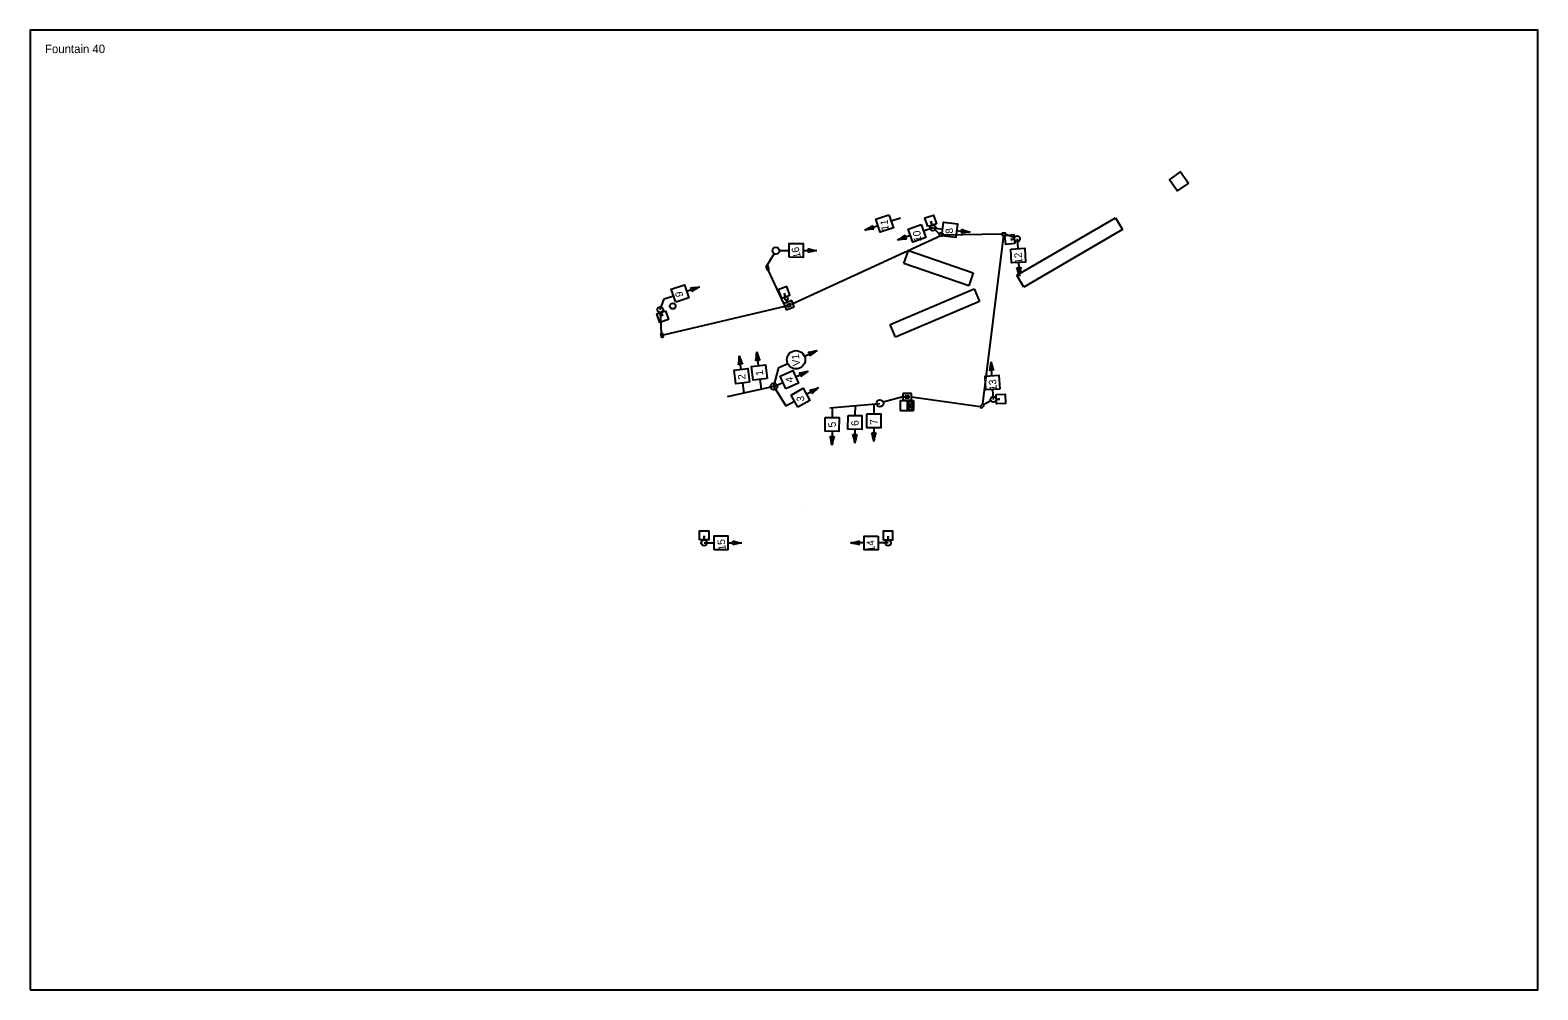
# Model space of a CAD drawing. Extents: x 994065 to 999017, y 1985203 to 1987174.
# Drawn here: x 994673 to 995333, y 1986754 to 1987174 of the extents above; entities that cross this region are included whole.
import ezdxf

# ---------------------------------------------------------------- set-up
doc = ezdxf.new("R2010")
doc.units = 0
for name, color, linetype in [('DSN_DRAIN_Analytics', 7, 'Continuous'), ('DSN_DRAIN_Analytics_ArDOT_BMCD_Rt', 7, 'Continuous'), ('DSN_DRAIN_Storm-Sewer', 7, 'Continuous'), ('EX_CONTOUR_ANNOT_MAJOR', 7, 'Continuous'), ('EX_CONTOUR_ANNOT_MINOR', 7, 'Continuous'), ('EX_TERRAIN', 7, 'Continuous'), ('EX_TERRAIN_BOUNDARY', 7, 'Continuous'), ('Level 23', 7, 'Continuous')]:
    doc.layers.add(name, color=color, linetype=linetype)

msp = doc.modelspace()

# ---------------------------------------------------------------- linework, layer by layer
at = {"layer": 'DSN_DRAIN_Analytics'}
for p, q in [((995105.13, 1987066.54), (995148.32, 1987091.73)), ((995148.32, 1987091.73), (995151.35, 1987086.55)), ((995151.35, 1987086.55), (995108.16, 1987061.35)), ((995055.7, 1987071.69), (995057.65, 1987077.37)), ((995057.65, 1987077.37), (995086.02, 1987067.63)), ((995084.07, 1987061.95), (995055.7, 1987071.69)), ((995086.02, 1987067.63), (995084.07, 1987061.95)), ((995108.16, 1987061.35), (995105.13, 1987066.54)), ((995049.65, 1987044.93), (995086.46, 1987060.61)), ((995086.46, 1987060.61), (995088.81, 1987055.09)), ((995088.81, 1987055.09), (995052.01, 1987039.41)), ((995052.01, 1987039.41), (995049.65, 1987044.93))]:
    msp.add_line(p, q, dxfattribs=at)
msp.add_lwpolyline([(995180.24, 1987106.86), (995175.31, 1987103.43), (995171.89, 1987108.36), (995176.82, 1987111.78)], close=True, dxfattribs=at)
at = {"layer": 'DSN_DRAIN_Analytics_ArDOT_BMCD_Rt'}
for points in [[(995066.09, 1987087.83), (995064.8, 1987091.62), (995068.58, 1987092.91), (995069.87, 1987089.12)], [(995104.22, 1987080.43), (995100.24, 1987079.98), (995099.79, 1987083.95), (995103.77, 1987084.4)], [(995004.4, 1987061.6), (995000.65, 1987060.22), (995002.04, 1987056.46), (995005.79, 1987057.85)], [(994951.32, 1987050.95), (994952.61, 1987047.17), (994948.82, 1987045.88), (994947.53, 1987049.66)], [(995096, 1987014.3), (995100, 1987014.47), (995100.17, 1987010.48), (995096.18, 1987010.3)], [(994966.22, 1986950.69), (994966.22, 1986954.69), (994970.22, 1986954.69), (994970.22, 1986950.69)], [(995046.75, 1986950.63), (995046.75, 1986954.63), (995050.75, 1986954.63), (995050.75, 1986950.63)]]:
    msp.add_lwpolyline(points, close=True, dxfattribs=at)
at = {"layer": 'DSN_DRAIN_Storm-Sewer'}
for p, q in [((995007.07, 1987054.2), (995071.86, 1987083.9)), ((995071.17, 1987084.62), (995069.33, 1987086.48)), ((995098.52, 1987084.58), (995072.83, 1987084.06)), ((995090.22, 1987010.35), (995099.4, 1987084.12)), ((995100.27, 1987084.58), (995104.08, 1987083.02)), ((994995.73, 1987070.64), (994998.92, 1987075.98)), ((995003.07, 1987054.2), (994996.26, 1987068.98)), ((994949.59, 1987041.15), (994949.09, 1987050.24)), ((995003.53, 1987052.95), (994950.23, 1987040.39)), ((995004.83, 1987054.85), (995004.45, 1987055.76)), ((995055.2, 1987013.31), (995046.59, 1987011)), ((995056.94, 1987011.7), (995057.08, 1987011.85)), ((995058.95, 1987013.31), (995089.01, 1987009.09)), ((995090.55, 1987010.04), (995093.73, 1987011.68))]:
    msp.add_line(p, q, dxfattribs=at)
at = {"layer": 'EX_CONTOUR_ANNOT_MAJOR'}
for p, q in [((995067.97, 1987089.87), (995067.14, 1987089.58)), ((995067.98, 1987088.48), (995067.55, 1987089.73)), ((995071.32, 1987085.05), (995071.03, 1987084.18)), ((995071.03, 1987084.18), (995072.68, 1987083.63)), ((995072.98, 1987084.5), (995071.32, 1987085.05)), ((995072.68, 1987083.63), (995072.98, 1987084.5)), ((995098.52, 1987085.04), (995098.52, 1987084.12)), ((995100.27, 1987085.04), (995098.52, 1987085.04)), ((995098.52, 1987084.12), (995100.27, 1987084.12)), ((995100.27, 1987084.12), (995100.27, 1987085.04)), ((995102.64, 1987082.7), (995102.73, 1987081.83)), ((995103.99, 1987082.41), (995102.69, 1987082.27)), ((994996.17, 1987070.78), (994995.29, 1987070.51)), ((994995.29, 1987070.51), (994995.82, 1987068.84)), ((994996.7, 1987069.11), (994996.17, 1987070.78)), ((994995.82, 1987068.84), (994996.7, 1987069.11)), ((995003.05, 1987058.24), (995003.87, 1987058.54)), ((995003.91, 1987057.16), (995003.46, 1987058.39)), ((994949.42, 1987050.31), (994949.85, 1987049.06)), ((995006.59, 1987055.5), (995003.07, 1987054.2)), ((995003.07, 1987054.2), (995004.08, 1987051.46)), ((995004.08, 1987051.46), (995007.6, 1987052.76)), ((995004.36, 1987053.61), (995006, 1987054.21)), ((995006, 1987054.21), (995004.36, 1987053.61)), ((995004.67, 1987052.75), (995004.36, 1987053.61)), ((995004.36, 1987053.61), (995004.67, 1987052.75)), ((995004.67, 1987052.75), (995006.32, 1987053.35)), ((995004.67, 1987052.75), (995006.32, 1987053.35)), ((995006.32, 1987053.35), (995006, 1987054.21)), ((995006.32, 1987053.35), (995006, 1987054.21)), ((995007.6, 1987052.76), (995006.59, 1987055.5)), ((994949.44, 1987048.92), (994950.26, 1987049.2)), ((994950.04, 1987041.25), (994949.14, 1987041.05)), ((994949.14, 1987041.05), (994949.52, 1987039.34)), ((994949.52, 1987039.34), (994950.41, 1987039.54)), ((994950.41, 1987039.54), (994950.04, 1987041.25)), ((995058.95, 1987014.77), (995055.2, 1987014.77)), ((995055.2, 1987014.77), (995055.2, 1987011.85)), ((995055.2, 1987011.85), (995058.95, 1987011.85)), ((995056.2, 1987012.85), (995056.2, 1987013.77)), ((995056.2, 1987013.77), (995057.95, 1987013.77)), ((995056.2, 1987013.77), (995056.2, 1987012.85)), ((995057.95, 1987013.77), (995056.2, 1987013.77)), ((995056.2, 1987012.85), (995057.95, 1987012.85)), ((995056.2, 1987012.85), (995057.95, 1987012.85)), ((995057.95, 1987012.85), (995057.95, 1987013.77)), ((995057.95, 1987012.85), (995057.95, 1987013.77)), ((995058.95, 1987011.85), (995058.95, 1987014.77)), ((995090.22, 1987010.35), (995089.01, 1987009.09)), ((995090.89, 1987009.72), (995090.22, 1987010.35)), ((995096.09, 1987012.3), (995097.41, 1987012.36)), ((995097.43, 1987011.92), (995097.39, 1987012.79)), ((995089.01, 1987009.09), (995089.68, 1987008.45)), ((995089.68, 1987008.45), (995090.89, 1987009.72)), ((994968.66, 1986952.01), (994967.78, 1986952.01)), ((994968.22, 1986950.69), (994968.22, 1986952.01)), ((995049.19, 1986951.95), (995048.31, 1986951.95)), ((995048.75, 1986950.63), (995048.75, 1986951.95))]:
    msp.add_line(p, q, dxfattribs=at)
at = {"layer": 'EX_CONTOUR_ANNOT_MINOR'}
for p, q in [((995054.18, 1987091.61), (995050.07, 1987090.21)), ((995044.34, 1987088.23), (995038.62, 1987086.28)), ((995058.53, 1987083.91), (995052.81, 1987081.97)), ((995068.38, 1987087.29), (995064.26, 1987085.89)), ((995068.38, 1987087.29), (995072.7, 1987086.79)), ((995078.72, 1987086.1), (995084.72, 1987085.4)), ((995001.13, 1987077.44), (995005.47, 1987077.42)), ((995011.54, 1987077.41), (995017.58, 1987077.37)), ((995105.24, 1987082.55), (995105.49, 1987078.21)), ((995105.87, 1987072.16), (995106.23, 1987066.13)), ((994950.69, 1987056.19), (994954.8, 1987057.59)), ((994960.53, 1987059.57), (994966.25, 1987061.51)), ((994949.03, 1987051.49), (994950.69, 1987056.19)), ((994984.37, 1987025.36), (994983.62, 1987031.35)), ((994992, 1987027.04), (994991.25, 1987033.03)), ((995012.13, 1987031.19), (995017.67, 1987033.66)), ((994998.75, 1987017.9), (995000.86, 1987026.18)), ((995000.86, 1987026.18), (995004.82, 1987027.94)), ((995008.25, 1987022.16), (995013.77, 1987024.61)), ((995094.2, 1987022.64), (995093.85, 1987028.67)), ((994985.68, 1987015.03), (994985.15, 1987019.35)), ((994993.31, 1987016.71), (994992.78, 1987021.02)), ((994998.75, 1987017.9), (995002.73, 1987019.67)), ((995013.03, 1987014.45), (995018.3, 1987017.4)), ((995003.95, 1987009.36), (995007.75, 1987011.48)), ((995042.54, 1987010.24), (995042.51, 1987005.9)), ((995094.84, 1987012.25), (995094.59, 1987016.59)), ((995024.26, 1987008.67), (995024.24, 1987004.32)), ((995034.27, 1987009.53), (995034.24, 1987005.18)), ((995024.23, 1986998.26), (995024.19, 1986992.22)), ((995034.23, 1986999.12), (995034.2, 1986993.08)), ((995042.5, 1986999.83), (995042.46, 1986993.79)), ((994968.21, 1986949.44), (994972.56, 1986949.43)), ((994978.62, 1986949.44), (994984.66, 1986949.43)), ((995038.34, 1986949.38), (995032.3, 1986949.4)), ((995048.75, 1986949.38), (995044.4, 1986949.39))]:
    msp.add_line(p, q, dxfattribs=at)
for points in [[(995049.09, 1987093.06), (995051.05, 1987087.32), (995045.31, 1987085.36), (995043.35, 1987091.11)], [(995072.34, 1987083.79), (995073.05, 1987089.81), (995079.07, 1987089.11), (995078.36, 1987083.08)], [(995063.29, 1987088.75), (995065.25, 1987083.01), (995059.51, 1987081.05), (995057.55, 1987086.79)], [(995005.46, 1987074.4), (995005.49, 1987080.46), (995011.55, 1987080.43), (995011.52, 1987074.37)], [(995102.48, 1987078.03), (995108.54, 1987078.39), (995108.89, 1987072.34), (995102.84, 1987071.98)], [(994955.78, 1987054.73), (994953.82, 1987060.47), (994959.56, 1987062.43), (994961.52, 1987056.69)], [(994988.14, 1987019.72), (994982.12, 1987018.97), (994981.37, 1987024.98), (994987.39, 1987025.74)], [(994995.77, 1987021.4), (994989.75, 1987020.64), (994989, 1987026.66), (994995.02, 1987027.41)], [(995003.95, 1987016.91), (995001.49, 1987022.46), (995007.03, 1987024.92), (995009.49, 1987019.38)], [(995009.22, 1987008.84), (995006.26, 1987014.14), (995011.55, 1987017.09), (995014.51, 1987011.8)], [(995097.6, 1987016.77), (995091.54, 1987016.41), (995091.19, 1987022.46), (995097.24, 1987022.82)], [(995021.22, 1987004.34), (995027.29, 1987004.3), (995027.25, 1986998.24), (995021.19, 1986998.28)], [(995031.23, 1987005.2), (995037.29, 1987005.17), (995037.26, 1986999.1), (995031.19, 1986999.14)], [(995039.49, 1987005.91), (995045.56, 1987005.88), (995045.52, 1986999.82), (995039.46, 1986999.85)], [(994972.55, 1986946.42), (994972.57, 1986952.48), (994978.63, 1986952.47), (994978.62, 1986946.4)], [(995044.41, 1986952.41), (995044.39, 1986946.35), (995038.33, 1986946.36), (995038.34, 1986952.42)]]:
    msp.add_lwpolyline(points, close=True, dxfattribs=at)
msp.add_circle((995008.47, 1987029.56), 4, dxfattribs=at)
for centre, radius, start, end in [((995025.04, 1987112.44), 29.47, 297.42123, 305.15935), ((995043.84, 1987057.27), 29.47, 92.46649, 100.2046), ((995043.6, 1987087.98), 1.63, 166.9656, 230.66024), ((995039.24, 1987108.13), 29.47, 297.42123, 305.15935), ((995057.8, 1987083.66), 1.63, 166.9656, 230.66024), ((995079.49, 1987086.01), 1.63, 321.44889, 25.14353), ((995085.7, 1987055.94), 29.47, 91.90453, 99.64264), ((995092.5, 1987113.82), 29.47, 246.94978, 254.68789), ((995012.31, 1987077.4), 1.63, 327.8422, 31.53683), ((995021.83, 1987048.21), 29.47, 98.29783, 106.03594), ((995022.15, 1987106.49), 29.47, 253.34308, 261.0812), ((995058.04, 1987052.96), 29.47, 92.46649, 100.2046), ((995105.92, 1987071.39), 1.63, 241.53304, 305.22767), ((995077.4, 1987060.01), 29.47, 11.98867, 19.72678), ((995135.58, 1987063.44), 29.47, 167.03392, 174.77204), ((994961.03, 1987090.52), 29.47, 272.46649, 280.2046), ((994961.27, 1987059.82), 1.63, 346.9656, 50.66024), ((994979.83, 1987035.35), 29.47, 117.42123, 125.15935), ((994954.16, 1987032.12), 29.47, 350.7729, 358.51101), ((995011.99, 1987039.34), 29.47, 195.72764, 203.46576), ((994961.79, 1987033.8), 29.47, 350.7729, 358.51101), ((995019.62, 1987041.02), 29.47, 195.72764, 203.46576), ((995009.85, 1987062.07), 29.47, 277.64538, 285.38349), ((995012.86, 1987031.51), 1.63, 352.14449, 55.83913), ((995033.55, 1987008.83), 29.47, 122.60013, 130.33824), ((994984.28, 1987026.13), 1.63, 65.27201, 128.96665), ((994991.91, 1987027.8), 1.63, 65.27201, 128.96665), ((995005.96, 1987053.03), 29.47, 277.64538, 285.38349), ((995008.96, 1987022.47), 1.63, 352.14449, 55.83913), ((995029.65, 1986999.78), 29.47, 122.60013, 130.33824), ((995064.5, 1987031.36), 29.47, 347.03392, 354.77204), ((995094.16, 1987023.41), 1.63, 61.53304, 125.22767), ((995122.68, 1987034.79), 29.47, 191.98867, 199.72678), ((995007.95, 1987044.99), 29.47, 282.82256, 290.56067), ((995036.36, 1986994.1), 29.47, 127.77731, 135.51542), ((995013.7, 1987014.83), 1.63, 357.32167, 61.01631), ((995034.23, 1986998.35), 1.63, 237.81428, 301.50891), ((995005.03, 1986988.84), 29.47, 8.26991, 16.00802), ((995042.49, 1986999.06), 1.63, 237.81428, 301.50891), ((995013.3, 1986989.55), 29.47, 8.26991, 16.00802), ((995071.58, 1986989.21), 29.47, 163.31516, 171.05328), ((995024.22, 1986997.48), 1.63, 237.81428, 301.50891), ((994995.03, 1986987.98), 29.47, 8.26991, 16.00802), ((995053.3, 1986987.63), 29.47, 163.31516, 171.05328), ((995063.31, 1986988.5), 29.47, 163.31516, 171.05328), ((994979.4, 1986949.44), 1.63, 328.01837, 31.713), ((994989.14, 1986978.56), 29.47, 253.51925, 261.25737), ((994989.01, 1986920.28), 29.47, 98.474, 106.21211), ((995027.95, 1986978.55), 29.47, 278.474, 286.21211), ((995027.82, 1986920.27), 29.47, 73.51925, 81.25737), ((995037.56, 1986949.39), 1.63, 148.01837, 211.713)]:
    msp.add_arc(centre, radius, start, end, dxfattribs=at)
at = {"layer": 'EX_TERRAIN'}
for p, q in [((995054.07, 1987011.7), (995059.81, 1987011.7)), ((995054.07, 1987011.7), (995054.07, 1987007.37)), ((995057.07, 1987011.7), (995057.07, 1987007.37)), ((995057.4, 1987011.37), (995057.4, 1987007.7)), ((995057.4, 1987011.37), (995059.48, 1987011.37)), ((995059.48, 1987011.35), (995057.4, 1987007.7)), ((995059.48, 1987007.7), (995057.41, 1987011.37)), ((995059.48, 1987011.37), (995059.48, 1987007.7)), ((995059.81, 1987011.7), (995059.81, 1987007.37)), ((995054.07, 1987007.37), (995059.81, 1987007.37)), ((995057.4, 1987007.7), (995059.48, 1987007.7))]:
    msp.add_line(p, q, dxfattribs=at)
at = {"layer": 'EX_TERRAIN_BOUNDARY'}
for p, q in [((994998.75, 1987017.9), (994978.24, 1987013.4)), ((994998.75, 1987017.9), (995003.95, 1987009.36)), ((995023.27, 1987008.58), (995045.19, 1987010.47))]:
    msp.add_line(p, q, dxfattribs=at)
for centre, radius in [((995068.38, 1987087.29), 1.25), ((995105.24, 1987082.55), 1.25), ((994999.63, 1987077.3), 1.5), ((995004.17, 1987056.45), 0.75), ((994949.03, 1987051.49), 1.25), ((994954.5, 1987053.06), 1.25), ((994998.75, 1987017.9), 1.5), ((995045.19, 1987010.47), 1.5), ((995094.84, 1987012.25), 1.25), ((994968.21, 1986949.44), 1.25), ((995048.75, 1986949.38), 1.25)]:
    msp.add_circle(centre, radius, dxfattribs=at)
at = {"layer": 'Level 23'}
msp.add_line((995013.11, 1986966.19), (995013.11, 1986966.19), dxfattribs=at)
msp.add_lwpolyline([(994673.18, 1986753.82), (995333.18, 1986753.82), (995333.18, 1987173.82), (994673.18, 1987173.82)], close=True, dxfattribs=at)

# ---------------------------------------------------------------- texts
at = {"layer": 'EX_CONTOUR_ANNOT_MINOR'}
for s, rotation, p in [('11', 96.06058, (995049.07, 1987086.26)), ('10', 96.06058, (995063.32, 1987081.41)), ('8', 96.06058, (995077.27, 1987084.92)), ('16', 102.45389, (995010.58, 1987074.48)), ('12', 96.06058, (995107.64, 1987071.85)), ('9', 96.06058, (994959.03, 1987057.17)), ('V1', 96.06058, (995010.26, 1987026.97)), ('1', 96.06058, (994994.15, 1987022.79)), ('2', 96.06058, (994986.41, 1987021.03)), ('4', 96.06058, (995007.26, 1987019.78)), ('13', 96.06058, (995096.45, 1987016.33)), ('3', 96.06058, (995012.13, 1987011.45)), ('5', 96.06058, (995025.99, 1987000.14)), ('6', 96.06058, (995035.99, 1987000.82)), ('7', 96.06058, (995044.31, 1987001.33)), ('15', 96.06058, (994977.75, 1986946.38)), ('14', 96.06058, (995043.05, 1986945.9))]:
    msp.add_text(s, height=3.25, rotation=rotation, dxfattribs=at).set_placement(p)
at = {"layer": 'Level 23'}
msp.add_text('Fountain 40', height=3.72, rotation=359.97484, dxfattribs=at).set_placement((994679.7, 1987163.78))

doc.saveas('drawing.dxf')
